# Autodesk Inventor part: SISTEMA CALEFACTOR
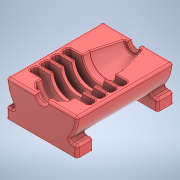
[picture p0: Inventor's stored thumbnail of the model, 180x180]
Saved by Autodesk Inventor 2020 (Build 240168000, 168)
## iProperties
Created: 2022-10
Part Number: SISTEMA CALEFACTOR
Material: Plástico PMMA
Document SubType Name: Modeling
Designer: SEBAS
Density: 1.188 g/cm^3
Appearance: Suave - Rojo
Author: SEBAS
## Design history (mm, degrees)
sketch "Boceto1"
  geometry: L1 (0, 0)-(25, 0); L2 (25, 0)-(25, -5); L3 (25, -5)-(23, -5); L4 (23, -5)-(18, -10); L5 (18, -10)-(18, -16); L6 (18, -16)-(5, -16); L7 (5, -16)-(5, -23); L8 (5, -23)-(18, -23); L9 (18, -23)-(18, -26); L10 (18, -26)-(5, -26); L11 (5, -26)-(5, -33); L12 (5, -33)-(18, -33); L13 (18, -33)-(18, -36); L14 (18, -36)-(5, -36); L15 (5, -36)-(5, -43); L16 (5, -43)-(18, -43); L17 (18, -43)-(18, -46); L18 (18, -46)-(5, -46); L19 (5, -46)-(5, -53); L20 (5, -53)-(18, -53); L21 (18, -53)-(18, -60); L22 (18, -60)-(25, -85); L23 (25, -85)-(25, -90); L24 (25, -90)-(0, -90); L25 (0, -90)-(0, 0); L26 (25, 0)-(33, 0); L27 (33, 0)-(33, -5); L28 (33, -5)-(25, -5); L29 (25, -5)-(25, 0); L30 (25, -90)-(33, -90); L31 (33, -90)-(33, -85); L32 (33, -85)-(25, -85); L33 (25, -85)-(25, -90); L34 (33, 0)-(33, -90)
  constraints: 68 end point, 15 perpendicular, 15 point on line, 7 collinear, 6 vertical alignment, 5 parallel, 3 horizontal, 1 vertical
  dimensions: "d0" = 80 vertical distance of L22.end L3.end; "d1" = 5 distance from line of L25 L6.end; "d2" = 3 distance of L8.end L9.end; "d3" = 7 distance of L6.end L7.end; "d4" = 7 distance of L20.end L21.end; "d5" = 25 vertical distance of L22.end L21.end; "d6" = 5 horizontal distance of L4.end L3.end; "d7" = 5 horizontal distance of L3.end L4.end; "d9" = 5 distance of L1.end L2.end; "d10" = 7 horizontal distance of L22.end L21.end; "d11" = 15 horizontal distance of L5.end L26.end
revolve "Revolución1" sketch "Boceto1" stored, may be unused: angle "d12" = 180 deg
sketch "Boceto2"
  geometry: L1 (-33, 0)-(33, 0) reference; C1 r 5 at (0, 0); 2 further points
  constraints: 1 centre point, 1 coincident, 1 midpoint
  dimensions: "d15" = 10 diameter of C1
extrude "Extrusión1" cut sketch "Boceto2" stored distance "d16" = 10; taper "d17" = 0 deg
sketch "Boceto3"
  geometry: L1 (33, -90)-(33, 0) reference; L2 (33, 0)-(5, 0) reference; L3 (-33, 0)-(-33, -90) reference; L4 (33, 0)-(-33, 0); L5 (-33, 0)-(-33, -90); L6 (-33, -90)-(33, -90); L7 (33, -90)-(33, 0); L8 (33, 0)-(-33, 0); L9 (-33, 0)-(-33, -15); L10 (-33, -15)-(33, -15); L11 (33, -15)-(33, 0); L12 (33, -90)-(-33, -90); L13 (-33, -90)-(-33, -75); L14 (-33, -75)-(33, -75); L15 (33, -75)-(33, -90); 8 further points
  constraints: 24 end point, 6 parallel, 3 horizontal, 3 perpendicular, 2 point on line
  dimensions: "d18" = 15 distance between parallel lines of L6 L14; "d19" = 15 distance between parallel lines of L2 L10
extrude "Extrusión2" join sketch "Boceto3" distance "d20" = 10; taper "d21" = 0 deg
fillet "Empalme3" dims "d22" = 2
fillet "Empalme4" dims "d23" = 2
fillet "Empalme5" dims "d24" = 1
node "Sólido1"
